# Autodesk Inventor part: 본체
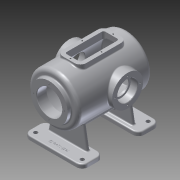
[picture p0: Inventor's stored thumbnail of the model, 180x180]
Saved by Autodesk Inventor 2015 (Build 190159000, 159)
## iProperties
Created: 2016-02
Part Number: 본체
Material: 알루미늄 6061
Document SubType Name: Modeling
Designer: mduedu
Density: 2.71 g/cm^3
Mass: 3305.63 g
Surface Area: 2487.05 cm^2
Volume: 1219.79 cm^3
Appearance: 알루미늄 - 평지
Author: mduedu
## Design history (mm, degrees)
sketch "스케치2"
  geometry: L1 (0, 100)-(0, -100); L2 (65, -87.083)-(65, 100); L3 (65, 100)-(0, 100); A1 r 170 centre (0, 70) between (0, -100) and (65, -87.083); 2 further points
  constraints: 6 end point, 2 point on circle, 1 centre point, 1 coincident, 1 horizontal, 1 midpoint, 1 parallel, 1 point on line, 1 vertical
  dimensions: "d3" = 200 distance of L1.start L1.end; "d5" = 130 diameter of L2 L1; "d6" = 170 radius of A1
revolve "회전1" sketch "스케치2" stored, may be unused: angle "d7" = 90 deg
sketch "스케치3"
  geometry: C1 r 47.5 at (0, 0); 1 further point
  constraints: 1 centre point, 1 coincident
  dimensions: "d8" = 95 diameter of C1
extrude "돌출2" join sketch "스케치3" distance "d10" = 10; taper "d11" = 0 deg
sketch "스케치5"
  geometry: L1 (47.5, 110)-(47.5, 100) reference; L2 (47.5, 100)-(65, 100) reference; L3 (65, 100)-(65, -87.083) reference; L4 (-65, -87.083)-(-65, 100) reference; L5 (-65, 100)-(-47.5, 100) reference; L6 (-47.5, 100)-(-47.5, 110) reference; L7 (-47.5, 110)-(47.5, 110) reference; L8 (55, 85)-(55, -80.25); L9 (0, 85)-(55, 85); L10 (0, 85)-(0, -90); A1 r 170 centre (0, 70) between (-65, -87.083) and (0, -100) reference; A2 r 170 centre (0, 70) between (0, -100) and (65, -87.083) reference; A3 r 160 centre (0, 70) between (0, -90) and (55, -80.25); 1 further point
  constraints: 6 end point, 2 point on circle, 1 centre point, 1 parallel, 1 perpendicular, 1 point on line, 1 vertical
  dimensions: "d13" = 10 distance between parallel lines of L3 L8; "d14" = 10 radial gap between concentric circles of A3 A1; "d15" = 15 distance between parallel lines of L9 L2
revolve "회전2" sketch "스케치5" stored, may be unused: angle "d16" = 90 deg
hole "구멍1" diameter "d19" = 65; stored, may be unused: countersink angle "d23" = 90 deg, drill point angle "d25" = 118 deg; dims "d17" = 10, "d18" = 10, "d20" = 6, "d21" = 4, "d22" = 2, "d24" = 8
node "작업 평면1"
sketch "스케치6"
  geometry: L1 (47.5, 110)-(-47.5, 110) reference; C1 r 40 at (0, -17); 1 further point
  constraints: 1 centre point, 1 vertical alignment
  dimensions: "d27" = 80 diameter of C1; "d29" = 127 distance from line of C1.centre L1
extrude "돌출3" join sketch "스케치6" stored distance "d30" = 10; taper "d31" = 0 deg
hole "구멍2" diameter "d34" = 42; stored, may be unused: countersink angle "d38" = 90 deg, drill point angle "d40" = 118 deg; dims "d32" = 10, "d33" = 10, "d35" = 6, "d36" = 52, "d37" = 18, "d39" = 8
sketch "스케치7" dims "d41" = 65
  geometry: C1 r 40 at (0, 0) reference; 3 further points
  constraints: 2 vertical alignment, 1 coincident, 2 other
hole "구멍3" sketch "스케치7" at (0, 32.5) diameter "d43" = 3.242; stored, may be unused: countersink angle "d47" = 90 deg, drill point angle "d49" = 118 deg; dims "d44" = 11, "d45" = 13, "d46" = 18, "d48" = 13
sketch "스케치8" dims "d53" = 80
  geometry: 3 further points
  constraints: 2 vertical alignment, 1 coincident, 2 other
hole "구멍4" sketch "스케치8" at (0, 40) diameter "d56" = 3.242; stored, may be unused: countersink angle "d60" = 90 deg, drill point angle "d62" = 118 deg; dims "d57" = 11, "d58" = 13, "d59" = 18, "d61" = 13
fillet "모깎기1" dims "d66" = 10
fillet "모깎기2" dims "d67" = 3
fillet "모깎기3" dims "d68" = 0.3
chamfer "모따기1" distance "d69" = 1; stored, may be unused: second distance "d70" = 2, angle "d71" = 45 deg
node "작업 평면2"
sketch "스케치9"
  geometry: L1 (75, 100)-(-75, 100); L2 (-75, 100)-(-75, -100); L3 (-75, -100)-(75, -100); L4 (75, -100)-(75, 100); 1 further point
  constraints: 8 end point, 2 parallel, 1 horizontal, 1 perpendicular
  dimensions: "d73" = 200 distance of L3.end L1.start; "d75" = 150 distance of L2.end L3.end; "d76" = 100 distance from line of L1 point (0, 0); "d77" = 75 distance from line of L4 point (0, 0)
extrude "돌출4" join sketch "스케치9" distance "d78" = 10; taper "d79" = 0 deg
sketch "스케치10"
  geometry: L1 (-75, -100)-(75, -100) reference; L2 (75, 100)-(-75, 100) reference; L3 (0, -100)-(0, 100); L4 (-75, 100)-(-75, -100) reference; L5 (75, -100)-(75, 100) reference; L6 (-75, 0)-(75, 0); L7 (-50, -63)-(50, -63); L8 (50, -63)-(50, -55); L9 (50, -55)-(-50, -55); L10 (-50, -55)-(-50, -63); L11 (-50, 63)-(50, 63); L12 (50, 63)-(50, 55); L13 (50, 55)-(-50, 55); L14 (-50, 55)-(-50, 63); 1 further point
  constraints: 20 end point, 4 midpoint, 4 symmetric about line, 2 parallel, 1 horizontal, 1 perpendicular, 1 other
  dimensions: "d80" = 8 distance of L9.end L7.start; "d82" = 100 distance of L7.start L7.end; "d83" = 55 distance between parallel lines of L9 L6
extrude "돌출5" join sketch "스케치10" stored distance "d84" = 10; taper "d85" = 0 deg
feature "면 기울기1" dims angle "d86" = 10 deg
sketch "스케치11"
  geometry: L1 (-110, 55)-(-51.482, 55) reference; L2 (-110, -55)-(-51.482, -55) reference; L3 (-95, 55)-(-95, -55); L4 (-65, 90)-(-65, -80.25) reference; 1 further point
  constraints: 2 end point, 2 point on line, 1 perpendicular
  dimensions: "d87" = 30 distance between parallel lines of L3 L4
feature "리브1" sketch "스케치11" dims "d88" = 1, "d89" = 8, "d90" = 0, "d91" = 0, "d92" = 1, "d93" = 1
sketch "스케치12"
  geometry: L1 (-110, 55)-(-51.482, 55) reference; L2 (-110, -55)-(-51.482, -55) reference; L3 (-110, 100)-(-110, -100) reference; L4 (-120, 152)-(-120, -142) reference; L5 (-110, 45)-(-120, 45); L6 (-120, 45)-(-120, -45); L7 (-120, -45)-(-110, -45); L8 (-110, -45)-(-110, 45); 1 further point
  constraints: 8 end point, 2 parallel, 2 point on line, 1 horizontal, 1 perpendicular
  dimensions: "d94" = 10 distance between parallel lines of L7 L2; "d95" = 10 distance between parallel lines of L1 L5
extrude "돌출6" cut sketch "스케치12" stored distance "d96" = 10; taper "d97" = 0 deg
fillet "모깎기4" dims "d98" = 15
sketch "스케치13"
  geometry: C1 r 5 at (-60, -85); C2 r 5 at (60, -85); C3 r 5 at (60, 85); C4 r 5 at (-60, 85); A1 r 15 centre (-60, -85) between (-75, -85) and (-60, -100) reference; A2 r 15 centre (60, -85) between (60, -100) and (75, -85) reference; A3 r 15 centre (60, 85) between (75, 85) and (60, 100) reference; A4 r 15 centre (-60, 85) between (-60, 100) and (-75, 85) reference; 1 further point
  constraints: 4 centre point, 4 coincident, 3 equal radius
  dimensions: "d99" = 10 diameter of C1
extrude "돌출7" cut sketch "스케치13" stored distance "d101" = 10; taper "d102" = 0 deg
fillet "모깎기5" dims "d103" = 3, "d104" = 3
fillet "모깎기6" dims "d105" = 3
sketch "스케치14"
  geometry: L1 (-60, -100)-(60, -100) reference; 2 further points
  constraints: 1 vertical alignment, 1 other
  dimensions: "d106" = 15 distance from line of point (0, -85) L1
feature "엠보싱1" sketch "스케치14" dims "d3" = 200, "d5" = 130, "d6" = 170, "d14" = 10, "d107" = 0.5, "d108" = 0
node "작업 평면3"
sketch "스케치15"
  geometry: L1 (-30, 60)-(30, 60); L2 (30, 60)-(30, -60); L3 (30, -60)-(-30, -60); L4 (-30, -60)-(-30, 60); 2 further points
  constraints: 8 end point, 2 parallel, 1 horizontal, 1 midpoint, 1 perpendicular, 1 vertical alignment
  dimensions: "d110" = 60 distance of L2.end L3.end; "d112" = 60 distance from line of L3 point (0, 0); "d113" = 120 distance of L1.end L2.end
extrude "돌출8" join sketch "스케치15" stored distance "d114" = 10; taper "d115" = 0 deg
fillet "모깎기7" dims "d116" = 15
sketch "스케치16"
  geometry: L1 (-30, -45)-(-30, 45) reference; L2 (-15, 60)-(15, 60) reference; L3 (30, 45)-(30, -45) reference; L4 (15, -60)-(-15, -60) reference; L5 (15, 50)-(-15, 50); L6 (-20, 45)-(-20, -45); L7 (-15, -50)-(15, -50); L8 (20, -45)-(20, 45); A1 r 15 centre (-15, -45) between (-30, -45) and (-15, -60) reference; A2 r 15 centre (-15, 45) between (-15, 60) and (-30, 45) reference; A3 r 15 centre (15, 45) between (30, 45) and (15, 60) reference; A4 r 15 centre (15, -45) between (15, -60) and (30, -45) reference; A5 r 5 centre (-15, 45) between (-15, 50) and (-20, 45); A6 r 5 centre (-15, -45) between (-20, -45) and (-15, -50); A7 r 5 centre (15, -45) between (15, -50) and (20, -45); A8 r 5 centre (15, 45) between (20, 45) and (15, 50); 1 further point
  constraints: 8 end point, 8 point on circle, 4 centre point, 7 other
  dimensions: "d117" = 10 distance between parallel lines of L6 L1
extrude "돌출9" cut sketch "스케치16" stored distance "d118" = 10; taper "d119" = 0 deg
fillet "모깎기8" dims "d120" = 3
sketch "스케치17"
  geometry: L1 (-30, -45)-(-30, 45) reference; L2 (-15, 60)-(15, 60) reference; L3 (30, 45)-(30, -45) reference; L4 (15, -60)-(-15, -60) reference; L5 (20, -45)-(20, 45) reference; L6 (15, 50)-(-15, 50) reference; L7 (-20, 45)-(-20, -45) reference; L8 (-15, -50)-(15, -50) reference; L9 (15, 55)-(-15, 55); L10 (-25, 45)-(-25, -45); L11 (-15, -55)-(15, -55); L12 (25, -45)-(25, 45); A1 r 15 centre (-15, 45) between (-15, 60) and (-30, 45) reference; A2 r 15 centre (15, 45) between (30, 45) and (15, 60) reference; A3 r 15 centre (15, -45) between (15, -60) and (30, -45) reference; A4 r 15 centre (-15, -45) between (-30, -45) and (-15, -60) reference; A5 r 5 centre (15, -45) between (15, -50) and (20, -45) reference; A6 r 5 centre (15, 45) between (20, 45) and (15, 50) reference; A7 r 5 centre (-15, 45) between (-15, 50) and (-20, 45) reference; A8 r 5 centre (-15, -45) between (-20, -45) and (-15, -50) reference; A9 r 10 centre (-15, 45) between (-15, 55) and (-25, 45); A10 r 10 centre (-15, -45) between (-25, -45) and (-15, -55); A11 r 10 centre (15, -45) between (15, -55) and (25, -45); A12 r 10 centre (15, 45) between (25, 45) and (15, 55); 5 further points
  constraints: 8 end point, 8 point on circle, 4 centre point, 4 midpoint, 7 other
  dimensions: "d121" = 5 distance between parallel lines of L10 L1
hole "구멍5" sketch "스케치17" at (0, 55), (25, 0), (0, -55), (-25, 0) diameter "d122" = 3.242; stored, may be unused: countersink angle "d126" = 90 deg, drill point angle "d128" = 118 deg; dims "d123" = 9, "d124" = 13, "d125" = 18, "d127" = 11
fillet "모깎기9" dims "d129" = 3
node "솔리드2"
pattern_circular "원형 패턴1" dims angle "d51" = 360 deg
mirror "대칭1"
pattern_circular "원형 패턴2" dims angle "d64" = 360 deg
node "절단 모서리 투영1"
node "절단 모서리 투영2"
node "절단 모서리 투영3"
other parameters: "d26" = 75
